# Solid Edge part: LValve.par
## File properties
Author: ptcarter
Last saved by: ptcarter
Revision: 32
Accuracy: 0.99
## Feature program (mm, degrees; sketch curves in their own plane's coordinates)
body "unnamed Body 1"
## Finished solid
Body 1: solid body, 17 faces, 26 edges, 22 vertices.
  Faces by surface: cylinder 9, plane 7, sphere 1
  Edges by curve: circle 18, line 6, curve on surface 2
Bounding box of the edges (mm; curved faces can reach further): 60.000 x 25.981 x 59.580, from (-30, -29.6862, -30) to (30, -3.7054, 29.5804).
Cylindrical faces by radius (mm): R1.5 x4, R3 x2, R7.5 x2, R15 x1
Spherical faces by radius (mm): R30 x1
Planar faces by outward normal: +y 4, +z 1, -y 2
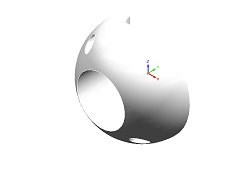
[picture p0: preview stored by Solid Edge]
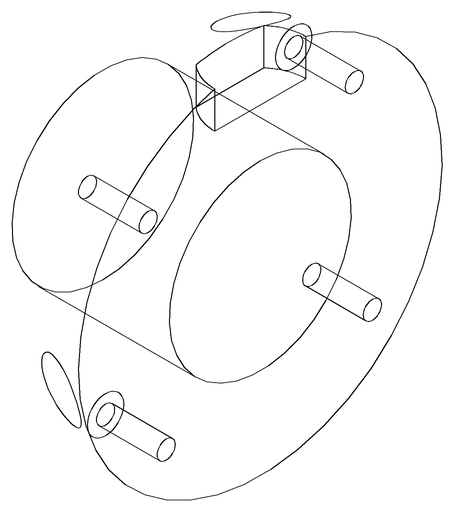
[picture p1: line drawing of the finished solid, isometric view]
